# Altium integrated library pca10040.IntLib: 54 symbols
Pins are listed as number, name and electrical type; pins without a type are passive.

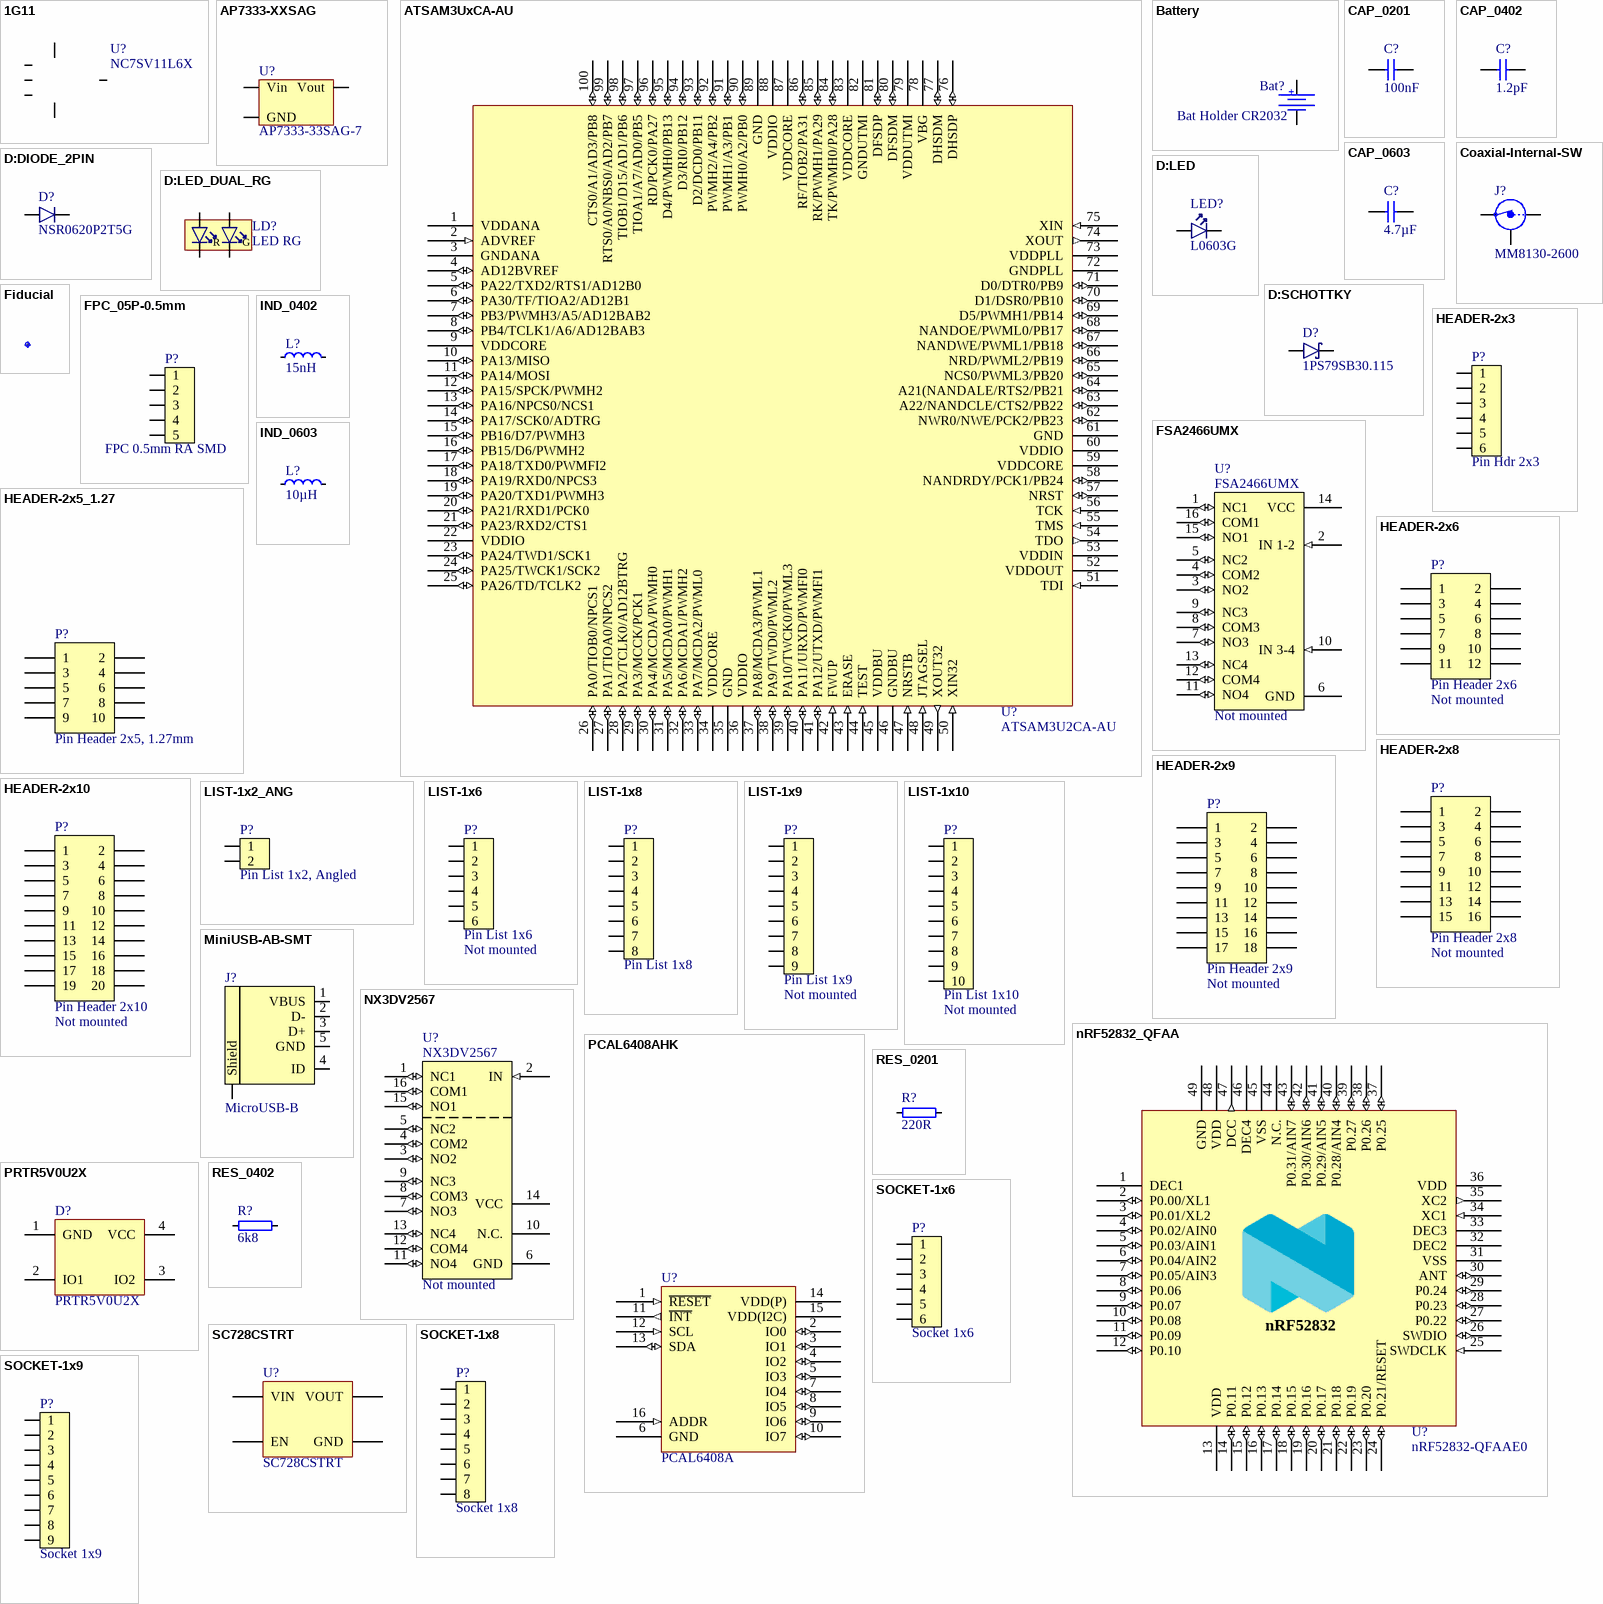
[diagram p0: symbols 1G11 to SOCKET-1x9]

## 1G11
designator U?, comment NC7SV11L6X
Single 3-input AND gate; Manufacturer: ON Semiconductor; Artikkelnr Noca: N.A.
footprint DFN1410-6N
pins: 1 A, 2 GND (power) "Ground", 3 B, 4 Y, 5 VCC (power), 6 C

## AP7333-XXSAG
designator U?, comment AP7333-33SAG-7
300mA, Low Quiescent Current, Fast Transient Low Dropout Linear Regulator; Manufacturer: Diodes Incorporated; Artikkelnr Noca: 17039216; Artikkelnr Simpro: N.A.
footprint SOT-23A
pins: 1 Vin, 2 Vout, 3 GND

## ATSAM3UxCA-AU
designator U?, comment ATSAM3U2CA-AU
IC MCU 32bit 128kB flash 100LQFP; Manufacturer: Atmel; 2nd source part number: 184-1662; Artikkelnr Noca: 15019073; Artikkelnr Simpro: N.A.
footprint TSQFP50P1600X1600X160-100N
pins: 1 VDDANA (power), 2 ADVREF (in), 3 GNDANA (power), 4 AD12BVREF (io), 5 PA22/TXD2/RTS1/AD12B0 (io), 6 PA30/TF/TIOA2/AD12B1 (io), 7 PB3/PWMH3/A5/AD12BAB2 (io), 8 PB4/TCLK1/A6/AD12BAB3 (io), 9 VDDCORE (power), 10 PA13/MISO (io), 11 PA14/MOSI (io), 12 PA15/SPCK/PWMH2 (io), 13 PA16/NPCS0/NCS1 (io), 14 PA17/SCK0/ADTRG (io), 15 PB16/D7/PWMH3 (io), 16 PB15/D6/PWMH2 (io), 17 PA18/TXD0/PWMFI2 (io), 18 PA19/RXD0/NPCS3 (io), 19 PA20/TXD1/PWMH3 (io), 20 PA21/RXD1/PCK0 (io), 21 PA23/RXD2/CTS1 (io), 22 VDDIO (power), 23 PA24/TWD1/SCK1 (io), 24 PA25/TWCK1/SCK2 (io), 25 PA26/TD/TCLK2 (io), 26 PA0/TIOB0/NPCS1 (io), 27 PA1/TIOA0/NPCS2 (io), 28 PA2/TCLK0/AD12BTRG (io), 29 PA3/MCCK/PCK1 (io), 30 PA4/MCCDA/PWMH0 (io), 31 PA5/MCDA0/PWMH1 (io), 32 PA6/MCDA1/PWMH2 (io), 33 PA7/MCDA2/PWML0 (io), 34 VDDCORE (power), 35 GND (power), 36 VDDIO (power), 37 PA8/MCDA3/PWML1 (io), 38 PA9/TWD0/PWML2 (io), 39 PA10/TWCK0/PWML3 (io), 40 PA11/URXD/PWMFI0 (io), 41 PA12/UTXD/PWMFI1 (io), 42 FWUP (in), 43 ERASE (in), 44 TEST (in), 45 VDDBU (power), 46 GNDBU (power), 47 NRSTB (in), 48 JTAGSEL (in), 49 XOUT32 (out), 50 XIN32 (in), 51 TDI (in), 52 VDDOUT (power), 53 VDDIN (power), 54 TDO (out), 55 TMS (in), 56 TCK (in), 57 NRST (io), 58 NANDRDY/PCK1/PB24 (io), 59 VDDCORE (power), 60 VDDIO (power), 61 GND (power), 62 NWR0/NWE/PCK2/PB23 (io), 63 A22/NANDCLE/CTS2/PB22 (io), 64 A21(NANDALE/RTS2/PB21 (io), 65 NCS0/PWML3/PB20 (io), 66 NRD/PWML2/PB19 (io), 67 NANDWE/PWML1/PB18 (io), 68 NANDOE/PWML0/PB17 (io), 69 D5/PWMH1/PB14 (io), 70 D1/DSR0/PB10 (io), 71 D0/DTR0/PB9 (io), 72 GNDPLL (power), 73 VDDPLL (power), 74 XOUT (out), 75 XIN (in), 76 DHSDP (io), 77 DHSDM (io), 78 VBG (power), 79 VDDUTMI (power), 80 DFSDM (io), 81 DFSDP (io), 82 GNDUTMI (power), 83 VDDCORE (power), 84 TK/PWMH0/PA28 (io), 85 RK/PWMH1/PA29 (io), 86 RF/TIOB2/PA31 (io), 87 VDDCORE (power), 88 VDDIO (power), 89 GND (power), 90 PWMH0/A2/PB0 (io), 91 PWMH1/A3/PB1 (io), 92 PWMH2/A4/PB2 (io), 93 D2/DCD0/PB11 (io), 94 D3/RI0/PB12 (io), 95 D4/PWMH0/PB13 (io), 96 RD/PCK0/PA27 (io), 97 TIOA1/A7/AD0/PB5 (io), 98 TIOB1/D15/AD1/PB6 (io), 99 RTS0/A0/NBS0/AD2/PB7 (io), 100 CTS0/A1/AD3/PB8 (io)

## Battery
designator Bat?, comment Bat Holder CR2032
Bat Holder CR2032 SMD; Manufacturer: Comfortable; Manufacturer Part Number: BC-2001; 2nd source part number: 165-0693; Artikkelnr Noca: 55089011; Artikkelnr Simpro: N.A.
footprint CR2032_HOLDER_SMD
pins: 1, 2

## CAP_0201
designator C?, comment 100nF
Capacitor, X5R, ±10%; Part Number: C0201-100n; Part number IPS: 00000001248; Note: 16V; Artikkelnr Noca: N.A.
footprint CAPC0603X03L_C
pins: 1, 2

## CAP_0402
designator C?, comment 1.2pF
Capacitor, NP0, ±0.1pF; Part Number: C0402-1.2p; Part number IPS: 00000005410; Note: 50V; Artikkelnr Noca: 20029157; Artikkelnr Simpro: N.A.
footprint CAPC1005X04L
pins: 1, 2

## CAP_0603
designator C?, comment 4.7µF
Capacitor, X5R, ±10%; Part Number: C0603-4µ7; Part number IPS: 00000007783; Note: 6.3V; Artikkelnr Noca: 20069060; Artikkelnr Simpro: N.A.
footprint CAPC1608X06L
pins: 1, 2

## Coaxial-Internal-SW
designator J?, comment MM8130-2600
Coaxial Connector with Switch; Manufacturer: Murata; 2nd source part number: 81-MM8130-2600RA2; Artikkelnr Noca: 55029011; Artikkelnr Simpro: N.A.
footprint COAXIAL-SWF
pins: 1 IN, 2 Shield, 3 OUT

## D:DIODE_2PIN
designator D?, comment NSR0620P2T5G
20V schottky barrier diode, Vf 350 mV @ 100 mA, Ir 2.0 µA @ 10 V, If 500 mA; Manufacturer: ON Semiconductor; Part number IPS: N.A.; Artikkelnr Noca: 10029169
footprint SODFL100X40-2N
pins: 1 C, 2 A

## D:LED
designator LED?, comment L0603G
LED SMARTLED GREEN 570NM 0603; Part Number: LG L29K Smartled Green; Manufacturer: Osram; Manufacturer Part Number: LG L29K-G2J1-24-Z; 2nd source part number: 720-LGL29KG2J124Z; Note: 2,24..5.6 mcd, Vfmin=1.7V; Artikkelnr Noca: 13019147; Artikkelnr Simpro: N.A.
footprint LED_0603_G
pins: 1 C, 2 A

## D:LED_DUAL_RG
designator LD?, comment LED RG
Ultra bright AlInGaP Bi-Color LED; Part Number: LTST-C195KGJRKT; Manufacturer: Lite-On Inc; 2nd source part number: 859-LTST-C195KGJRKT; Artikkelnr Noca: 13019145; Artikkelnr Simpro: N.A.
footprint LED_DUAL_0606
pins: 1 A2, 2 A1, 3 C2, 4 C1

## D:SCHOTTKY
designator D?, comment 1PS79SB30.115
Diode Schottky Vf=0.38, Vr=40V, If=200mA, Ir=500nA; Manufacturer: NXP; 2nd source part number: 873-4097; Artikkelnr Noca: 10029120; Artikkelnr Simpro: N.A.
footprint SOD-523
pins: 1 A, 3 C

## Fiducial
designator Fid?, comment Fiducial mark  (value not drawn)  (no BOM)
Part Number: Fid-Mark; Artikkelnr Noca: N.A.
footprint Fiducial

## FPC_05P-0.5mm
designator P?, comment FPC 0.5mm RA SMD
0.5mm FPC, 5P,Right Angle SMT,Double Contact,H=1.2mm,White, Tin plated; Part Number: FPC_05P-0.5mm-RA-SMD; Manufacturer: W-CON; Manufacturer Part Number: 5141-05RZDNWR01; 2nd source part number: WM9836CT-ND; Part number IPS: 00000007792; Artikkelnr Noca: 55010020; Artikkelnr Simpro: N.A.
footprint FPC_05P-0.5mm-RA-SMD
pins: 1, 2, 3, 4, 5

## FSA2466UMX
designator U?  Assembly: Not mounted
Data / Audio Low-Voltage Dual DPDT Analog Switch; Manufacturer: Fairchild Semiconductor; 2nd source part number: 512-FSA2466UMX; Artikkelnr Noca: 15070069; Artikkelnr Simpro: N.A.
footprint XQFN40P180X260X50-16N
pins: 1 NC1 (io), 2 IN 1-2 (in), 3 NO2 (io), 4 COM2 (io), 5 NC2 (io), 6 GND (power), 7 NO3 (io), 8 COM3 (io), 9 NC3 (io), 10 IN 3-4 (in), 11 NO4 (io), 12 COM4 (io), 13 NC4 (io), 14 VCC (power), 15 NO1 (io), 16 COM1 (io)

## HEADER-2x3
designator P?, comment Pin Hdr 2x3
Pin Header 2x3, 2.54mm (100mil) SMD; Part Number: Pin Header 2x3 SMD; Manufacturer: W-CON; Manufacturer Part Number: 1125-1203S0M116R1; 2nd source part number: TSM-103-01-L-DV; Artikkelnr Noca: 55010007; Artikkelnr Simpro: N.A.
footprint HDR_2x3-SMD
pins: 1, 2, 3, 4, 5, 6

## HEADER-2x5_1.27
designator P?, comment Pin Header 2x5, 1.27mm
Pin Header 2x5, 1.27mm (50mil), SMD, Keying Shroud; Part Number: Pin Header 2x5 SMD, 1.27mm, KS; Manufacturer: W-CON; Manufacturer Part Number: 3132-10MS0BK00R1; 2nd source part number: FTSH-105-01-F-DV-K; Artikkelnr Noca: 55010009; Artikkelnr Simpro: N.A.
footprint HDR_2x5-SMD-1.27mm-K
pins: 1, 2, 3, 4, 5, 6, 7, 8, 9, 10

## HEADER-2x6
designator P?, comment Pin Header 2x6  Assembly: Not mounted
Pin Header 2x6, 2.54mm (100mil); Part Number: Pin Header 2x6, N.C.; Artikkelnr Noca: N.A.
footprint HDR_2x6-NC
pins: 1, 2, 3, 4, 5, 6, 7, 8, 9, 10, 11, 12

## HEADER-2x8
designator P?, comment Pin Header 2x8  Assembly: Not mounted
Pin Header 2x8, 2.54mm (100mil); Part Number: Pin Header 2x8, N.C.; Artikkelnr Noca: N.A.
footprint HDR_2x8-NC
pins: 1, 2, 3, 4, 5, 6, 7, 8, 9, 10, 11, 12, 13, 14, 15, 16

## HEADER-2x9
designator P?, comment Pin Header 2x9  Assembly: Not mounted
Pin Header 2x9, 2.54mm (100mil); Part Number: Pin Header 2x9, N.C.; Artikkelnr Noca: N.A.
footprint HDR_2x9-NC
pins: 1, 2, 3, 4, 5, 6, 7, 8, 9, 10, 11, 12, 13, 14, 15, 16, 17, 18

## HEADER-2x10
designator P?, comment Pin Header 2x10  Assembly: Not mounted
Pin Header 2x10, 2.54mm (100mil); Part Number: Pin Header 2x10, N.C.; Artikkelnr Noca: N.A.
footprint HDR_2x10-NC
pins: 1, 2, 3, 4, 5, 6, 7, 8, 9, 10, 11, 12, 13, 14, 15, 16, 17, 18, 19, 20

## IND_0402
designator L?, comment 15nH
Inductor, 320mA, ±5%; Part Number: L0402-15n; Manufacturer: Taiyo Yuden; Manufacturer Part Number: HK100515NJ-T; 2nd source part number: 658-1328; Part number IPS: 00000003215; Note: High frequency chip inductor ±10%; Artikkelnr Noca: 33029323; Artikkelnr Simpro: N.A.
footprint INDC1005X04L
pins: 1, 2

## IND_0603
designator L?, comment 10µH
Inductor, 80mA, ±10%; Part Number: L0603-10µ; Manufacturer: Taiyo Yuden; Manufacturer Part Number: LBMF1608T100K; 2nd source part number: 178-6105; Part number IPS: 00000007794; Note: LBMF1608T100K 10µH 80mA 0603; Artikkelnr Noca: 33029314; Artikkelnr Simpro: N.A.
footprint INDC1608X06L
pins: 1, 2

## LIST-1x2_ANG
designator P?, comment Pin List 1x2, Angled
Pin List 1x2, 2.54mm (100mil), Right Angled, SMD; Part Number: Pin List Ang 1x2 SMD, 2.54mm; Manufacturer: W-CON; Manufacturer Part Number: 1125B-1102S0Z135R2; 2nd source part number: TSM-102-01-L-SH-A; Artikkelnr Noca: 55010023; Artikkelnr Simpro: N.A.
footprint LIST_ANG_1x2-SMD-2.54MM
pins: 1, 2

## LIST-1x6
designator P?, comment Pin List 1x6  Assembly: Not mounted
Pin List 1x6, 2.54mm (100mil), SMD; Part Number: Pin List 1x6 SMD, N.C.; Manufacturer: W-CON; Manufacturer Part Number: 1125-1106S0M116R2; Part number IPS: N.A.; Artikkelnr Noca: 55010026
footprint LIST_1x6_SMD-NC
pins: 1, 2, 3, 4, 5, 6

## LIST-1x8
designator P?, comment Pin List 1x8
Pin List 1x8, 2.54mm (100mil), SMD; Part Number: Pin List 1x8 SMD; Manufacturer: W-CON; Manufacturer Part Number: 1125-1108S0M116R2; Part number IPS: N.A.; Artikkelnr Noca: 55010006
footprint LIST_1x8_SMD
pins: 1, 2, 3, 4, 5, 6, 7, 8

## LIST-1x9
designator P?, comment Pin List 1x9  Assembly: Not mounted
Pin List 1x9, 2.54mm (100mil), SMD; Part Number: Pin List 1x9 SMD, N.C.; Manufacturer: W-CON; Manufacturer Part Number: 1125-1109S0M116R2; Part number IPS: N.A.; Artikkelnr Noca: 55010024
footprint LIST_1x9_SMD-NC
pins: 1, 2, 3, 4, 5, 6, 7, 8, 9

## LIST-1x10
designator P?, comment Pin List 1x10  Assembly: Not mounted
Pin List 1x10, 2.54mm (100mil), SMD; Part Number: Pin List 1x10 SMD, N.C.; Manufacturer: W-CON; Manufacturer Part Number: 1125-1110S0M116R2; Part number IPS: N.A.; Artikkelnr Noca: 55010028
footprint LIST_1x10_SMD-NC
pins: 1, 2, 3, 4, 5, 6, 7, 8, 9, 10

## MiniUSB-AB-SMT
designator J?, comment MicroUSB-B
MicroUSB-B-SMT; Part Number: USB-Micro-B-RA-SMD-PiP; Manufacturer: Allen Creations Corp.; Manufacturer Part Number: AJU55-BS2111-L; 2nd source part number: 609-4616-1-ND; Part number IPS: 00000007790; Artikkelnr Noca: 55029020; Artikkelnr Simpro: N.A.
footprint USB-Micro-B-RA-SMD-PiP
pins: 1 VBUS (power), 2 D-, 3 D+, 4 ID, 5 GND (power), 6 Shield (power)

## nRF52832_QFAA
designator U?, comment nRF52832-QFAAE0
Multi-protocol Bluetooth Low Energy, ANT and 2.4GHz proprietary system-on-chip; Manufacturer: Nordic Semiconductor; Artikkelnr Noca: N.A.
footprint QFN40P600X600X90-48N
pins: 1 DEC1 (power), 2 P0.00/XL1 (io), 3 P0.01/XL2 (io), 4 P0.02/AIN0 (io), 5 P0.03/AIN1 (io), 6 P0.04/AIN2 (io), 7 P0.05/AIN3 (io), 8 P0.06 (io), 9 P0.07 (io), 10 P0.08 (io), 11 P0.09 (io), 12 P0.10 (io), 13 VDD (power), 14 P0.11 (io), 15 P0.12 (io), 16 P0.13 (io), 17 P0.14 (io), 18 P0.15 (io), 19 P0.16 (io), 20 P0.17 (io), 21 P0.18 (io), 22 P0.19 (io), 23 P0.20 (io), 24 P0.21/RESET (io), 25 SWDCLK (in), 26 SWDIO (io), 27 P0.22 (io), 28 P0.23 (io), 29 P0.24 (io), 30 ANT (io), 31 VSS (power), 32 DEC2 (power), 33 DEC3 (power), 34 XC1 (in), 35 XC2 (out), 36 VDD (power), 37 P0.25 (io), 38 P0.26 (io), 39 P0.27 (io), 40 P0.28/AIN4 (io), 41 P0.29/AIN5 (io), 42 P0.30/AIN6 (io), 43 P0.31/AIN7 (io), 44 N.C. (power), 45 VSS (power), 46 DEC4 (power), 47 DCC (out), 48 VDD (power), 49 GND (power)

## NX3DV2567
designator U?  Assembly: Not mounted
Low-ohmic four-pole double-throw analog switch; Part Number: NX3DV2567GU; Manufacturer: NXP Semiconductors; 2nd source part number: 771-NX3DV2567GU115; Part number IPS: 00000007816; Artikkelnr Noca: 15079317; Artikkelnr Simpro: N.A.
footprint XQFN40P180X260X50-16N
pins: 1 NC1 (io), 2 IN (in), 3 NO2 (io), 4 COM2 (io), 5 NC2 (io), 6 GND (power), 7 NO3 (io), 8 COM3 (io), 9 NC3 (io), 10 N.C., 11 NO4 (io), 12 COM4 (io), 13 NC4 (io), 14 VCC (power), 15 NO1 (io), 16 COM1 (io)

## PCAL6408AHK
designator U?, comment PCAL6408A
8-bit I2C-bus I/O expander with interrupt output; Part Number: PCAL6408AHK; Manufacturer: NXP Semiconductors; 2nd source part number: 771-PCAL6408AHKX; Artikkelnr Noca: 15079321; Artikkelnr Simpro: N.A.
footprint XQFN40P180X260X50-16N
pins: 1 ~{RESET} (in), 2 IO0 (io), 3 IO1 (io), 4 IO2 (io), 5 IO3 (io), 6 GND (power), 7 IO4 (io), 8 IO5 (io), 9 IO6 (io), 10 IO7 (io), 11 ~{INT} (out), 12 SCL (in), 13 SDA (io), 14 VDD(P) (power) "VDD 2.3V - 5.5V", 15 VDD(I2C) (power), 16 ADDR (in)

## PRTR5V0U2X
designator D?
Ultra low capacitance double rail-to-rail ESD protection diode; Manufacturer: NXP; 2nd source part number: 152-4157; Artikkelnr Noca: 10069015; Artikkelnr Simpro: N.A.
footprint SOT190P230X110-4L
pins: 1 GND, 2 IO1, 3 IO2, 4 VCC

## RES_0201
designator R?, comment 220R
Resistor, ±1%, 0.05W; Part Number: R0201-220; Part number IPS: 00000000863; Note: Chip Res 1%; Artikkelnr Noca: N.A.
footprint RESC0603X03L_C
pins: 1, 2

## RES_0402
designator R?, comment 6k8
Resistor, ±1%, 0.063W; Part Number: R0402-6k8; Note: Chip Res 1%; Artikkelnr Noca: 27049093; Artikkelnr Simpro: N.A.; Value Ohm: 6800
footprint RESC1005X04L
pins: 1, 2

## SC728CSTRT
designator U?
Semtech, 2A Low Vin, Very Low Ron, Load Switch, 4DSBGA; Manufacturer: Semtech Corporation; 2nd source part number: 947-SC728CSTRT; Artikkelnr Noca: 15070081; Artikkelnr Simpro: N.A.
footprint BGA4C40P2X2_76X76X62
pins: A1 VOUT, A2 VIN, B1 GND, B2 EN

## SOCKET-1x6
designator P?, comment Socket 1x6
Socket 1x6, 2.54mm (100mil), SMD; Part Number: Socket 1x6 SMD; Manufacturer: W-CON; Manufacturer Part Number: 2171-106MS0CUNR1; 2nd source part number: SSM-106-F-SV-P-TR; Artikkelnr Noca: 55030001; Artikkelnr Simpro: N.A.
footprint SOCKET_1x6_SMD
pins: 1, 2, 3, 4, 5, 6

## SOCKET-1x8
designator P?, comment Socket 1x8
Socket 1x8, 2.54mm (100mil), SMD; Part Number: Socket 1x8 SMD; Manufacturer: W-CON; Manufacturer Part Number: 2171-108MS0CUNR1; 2nd source part number: SSM-108-F-SV-P-TR; Artikkelnr Noca: 55030002; Artikkelnr Simpro: N.A.
footprint SOCKET_1x8_SMD
pins: 1, 2, 3, 4, 5, 6, 7, 8

## SOCKET-1x9
designator P?, comment Socket 1x9
Socket 1x9, 2.54mm (100mil), SMD; Part Number: Socket 1x9 SMD; Manufacturer: W-CON; Manufacturer Part Number: 2171-109MS0CUNR1; 2nd source part number: SSM-109-L-SV; Artikkelnr Noca: 55030003; Artikkelnr Simpro: N.A.
footprint SOCKET_1x9_SMD
pins: 1, 2, 3, 4, 5, 6, 7, 8, 9

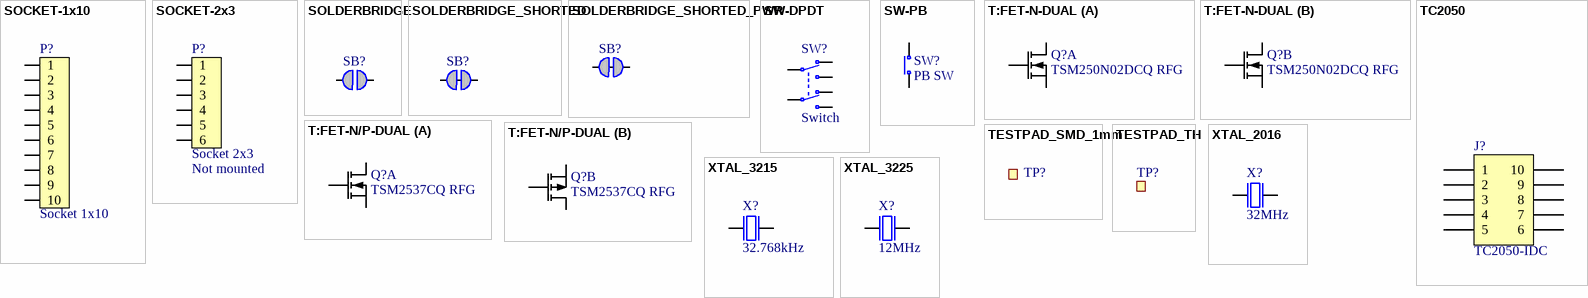
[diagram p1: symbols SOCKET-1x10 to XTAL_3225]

## SOCKET-1x10
designator P?, comment Socket 1x10
Socket 1x10, 2.54mm (100mil), SMD; Part Number: Socket 1x10 SMD; Manufacturer: W-CON; Manufacturer Part Number: 2171-110MS0CUNR1; 2nd source part number: SSM-110-F-SV-P-TR; Artikkelnr Noca: 55030004; Artikkelnr Simpro: N.A.
footprint SOCKET_1x10_SMD
pins: 1, 2, 3, 4, 5, 6, 7, 8, 9, 10

## SOCKET-2x3
designator P?, comment Socket 2x3  Assembly: Not mounted
Socket 2x3, 2.54mm (100mil), SMD; Part Number: Socket 2x3 SMD Bottom, N.C.; Manufacturer: W-CON; Manufacturer Part Number: 2171-203MS0CUNR1; Part number IPS: N.A.; Artikkelnr Noca: 55030010
footprint SOCKET_2x3_SMD-2.54mm-bottom-NC
pins: 1, 2, 3, 4, 5, 6

## SOLDERBRIDGE
designator SB?, comment Solderbridge  (value not drawn)  (no BOM)
Artikkelnr Noca: N.A.
footprint Solderbridge
pins: 1 0, 2 1

## SOLDERBRIDGE_SHORTED
designator SB?, comment Solderbridge  (value not drawn)  (net tie, no BOM)
Shorted Solderbridge; Part Number: Solderbridge Shorted; Artikkelnr Noca: N.A.
footprint Solderbridge_Shorted
pins: 1 0, 2 1

## SOLDERBRIDGE_SHORTED_PWR
designator SB?, comment Solderbridge  (value not drawn)  (net tie, no BOM)
Shorted Solderbridge Power; Part Number: Solderbridge Shorted Power; Artikkelnr Noca: N.A.
footprint Solderbridge_Shorted_Power
pins: 1 0, 2 1

## SW-DPDT
designator SW?, comment Switch
SMD slide Switch (ON-ON); Part Number: Switch-Slide-DPDT-8.5x3.6mm; Manufacturer: Dailywell; Manufacturer Part Number: SS206VM-G2-LLR-R; Part number IPS: N.A.; Artikkelnr Noca: 50019107
footprint Switch-Slide-DPDT-8.5x3.6mm
pins: 1 N.O-1, 2 COM-1, 3 N.C-1, 4 N.O-2, 5 COM-2, 6 N.C-2

## SW-PB
designator SW?, comment PB SW
Tactile Switch, SPNO, SMD, 160gf, 6.2x6.3x2.5mm; Part Number: Switch-PB-6.2x6.3mm-SMD; Manufacturer: Dailywell; Manufacturer Part Number: TS604VM1-025BR-R; 2nd source part number: 688-SKHUALE010; Part number IPS: 00000007812; Artikkelnr Noca: 50019106; Artikkelnr Simpro: N.A.
footprint Switch-PB-6.2x6.3mm-SMD
pins: 1 N.O, 2 COM

## T:FET-N-DUAL
designator Q?, comment TSM250N02DCQ RFG
Dual N Ch MOFET, 5.8A, 55mOhm max, 620mW; Manufacturer: Taiwan Semiconductor; Artikkelnr Noca: N.A.
footprint DFN65P200X200X80_HS-6N
part A pins: 1 S1, 2 G1, 6 D1
part B pins: 3 D2, 4 S2, 5 G2

## T:FET-N/P-DUAL
designator Q?, comment TSM2537CQ RFG
Dual N & P Ch MOFET, 11.6A/9A, 90mOhm max, 6.25W; Manufacturer: Taiwan Semiconductor; Artikkelnr Noca: N.A.
footprint DFN65P200X200X80_HS-6N
part A pins: 1 S1, 2 G1, 6 D1
part B pins: 3 D2, 4 S2, 5 G2

## TC2050
designator J?, comment TC2050-IDC  (no BOM)
CBL PLUG-OF-NAILS 10-PIN; Part Number: TC2050-IDC-NLFP; Manufacturer: Tag-Connect LLC; Artikkelnr Noca: N.A.
footprint TC2050-IDC-NLFP
pins: 1, 2, 3, 4, 5, 6, 7, 8, 9, 10

## TESTPAD_SMD_1mm
designator TP?, comment Ø1.0mm,SMD  (value not drawn)  (no BOM)
1.0mm circular SMD testpad; Part Number: TP_SMD_Ø1.0MM; Manufacturer: Nordic Semiconductor; Artikkelnr Noca: N.A.
footprint TP_SMD_Ø1.0mm
pins: 1

## TESTPAD_TH
designator TP?, comment TP  (value not drawn)  (no BOM)
Testpoint, through hole; Part Number: Testpoint TH; Artikkelnr Noca: N.A.
footprint TESTPAD-TH
pins: 1

## XTAL_2016
designator X?, comment 32MHz
XTAL SMD 2016, 32MHz, Cl=8pF, Tol: ±10ppm, Stab: ±10ppm; Part Number: XTAL_SMD2016_32MHz_8pF_Epson; Manufacturer: Epson Toyocom; Manufacturer Part Number: Q22FA12800025; Note: XTAL SMD 32.000MHz; Artikkelnr Noca: 22019238; Artikkelnr Simpro: N.A.
footprint BT-XTAL_2016
pins: 1 inp, 2 GND hidden to GND, 3 out, 4 GND hidden to GND

## XTAL_3215
designator X?, comment 32.768kHz
XTAL SMD 3215, 32.768kHz, 9pF, ±20ppm; Part Number: XTAL_FC-135 32.768k; Manufacturer: Epson Toyocom; Manufacturer Part Number: FC-135 32.768KHZ ±20PPM,9.0PF; 2nd source part number: 127-8037; Note: XTAL SMD 32.768kHz, 3215; Artikkelnr Noca: 22019091; Artikkelnr Simpro: N.A.
footprint XTAL_3215
pins: 1 inp, 2 out

## XTAL_3225
designator X?, comment 12MHz
XTAL SMD 3225, 12MHz, Cl=18pF, Tol: ±30ppm, Stab: ±30ppm; Part Number: XTAL_SMD3225_12MHz_18pF_TXC; Manufacturer: TXC Corporation; Manufacturer Part Number: 7M-12.000MAAJ-T; 2nd source part number: 184-2056; Note: XTAL SMD 12.000MHz; Artikkelnr Noca: 22019166; Artikkelnr Simpro: N.A.
footprint BT-XTAL_3225
pins: 1 inp, 2 GND hidden to GND, 3 out, 4 GND hidden to GND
